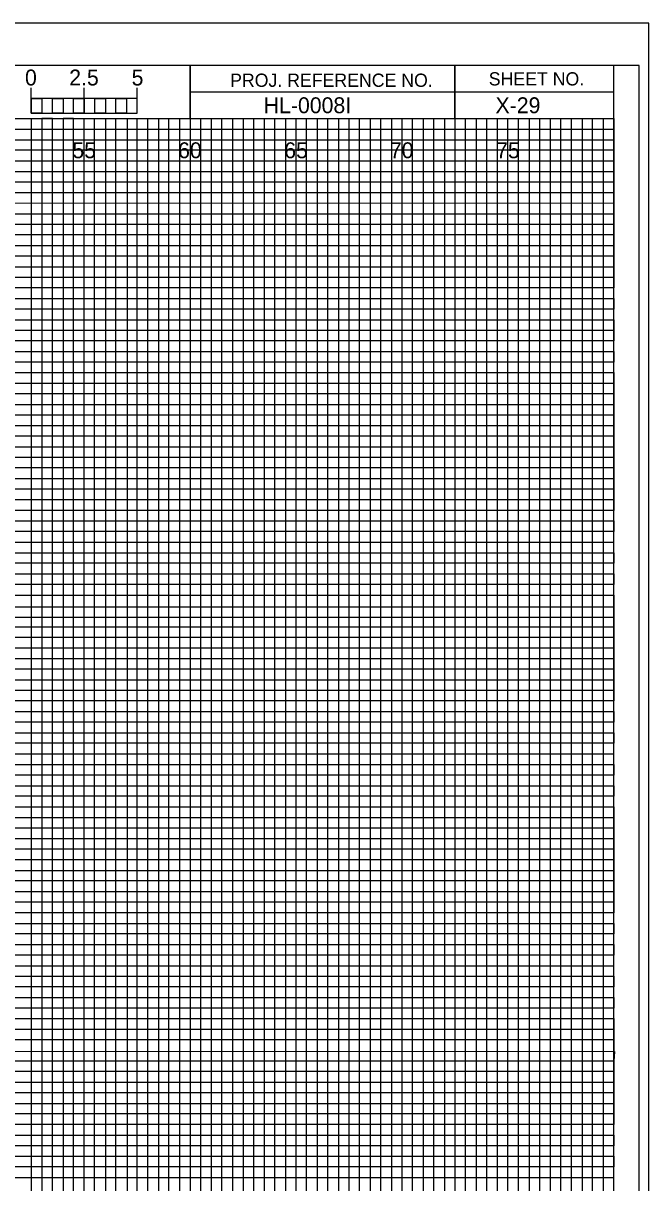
# Model space of a CAD drawing. Extents: x -7 to 162, y -2 to 217.
# Drawn here: x 132.1 to 161.7, y 162.2 to 217 of the extents above; entities that cross this region are included whole.
import ezdxf

# ---------------------------------------------------------------- set-up
doc = ezdxf.new("R2010")
doc.units = 0
for name, color, linetype in [('Exist Cross Section Cell', 7, 'Continuous'), ('Exist XS Center Line Elevation Label', 7, 'Continuous'), ('Exist XS Ground Line', 7, 'Continuous'), ('Prop CMT Pvmt Course 1 CG', 7, 'Continuous'), ('Prop CMT Pvmt Course 2', 7, 'Continuous'), ('Prop CMT Pvmt Course 3', 7, 'Continuous'), ('Prop CMT Shld Paved Course 1', 7, 'Continuous'), ('Prop CMT Shld Paved Course 2', 7, 'Continuous'), ('Prop CMT Shld Paved Course 3', 7, 'Continuous'), ('Prop CMT Slope Grass', 7, 'Continuous'), ('Prop CMT Subgrade Earthwork', 7, 'Continuous'), ('Scratch_Level_3', 7, 'Continuous')]:
    doc.layers.add(name, color=color, linetype=linetype)

msp = doc.modelspace()

# ---------------------------------------------------------------- linework, layer by layer
at = {"layer": 'Prop CMT Pvmt Course 2'}
msp.add_line((0, 212), (160, 212), dxfattribs=at)
for points in [[(0, 211.5), (135, 211.5), (160, 211.5)], [(160, 211), (0, 211)], [(0, 210.5), (160, 210.5)], [(160, 209.5), (0, 209.5)], [(0, 209), (160, 209)], [(160, 208.5), (0, 208.49)], [(0, 208), (160, 208)], [(160, 207), (0, 207)], [(0, 206.5), (160, 206.5), (160, 206), (0, 206)], [(0, 205.5), (160, 205.5), (160, 204.5), (0, 204.5)], [(0, 204), (160, 204), (160, 203.5), (0, 203.5)], [(0, 203), (160, 203), (160, 202), (0, 202)], [(0, 201.5), (160, 201.5), (160, 201), (0, 201)], [(0, 200.5), (160, 200.5), (160, 199.5), (0, 199.5)], [(0, 199), (160, 199), (160, 198.5), (0, 198.5)], [(0, 198), (160, 198), (160, 196.975), (160, 196.5), (160, 196), (0, 196)], [(0, 197), (160, 197), (160, 196.5), (0, 196.5)], [(0, 195.5), (160, 195.5), (160, 194.5), (0, 194.515)], [(0, 194.515), (160, 194.5), (160, 194), (0, 194)], [(0, 193.5), (160, 193.5), (160, 193), (0, 193)], [(0, 192), (160, 192), (160, 191.5), (0, 191.5)], [(0, 191), (160, 191), (160, 190.5), (0, 190.5)], [(-0.035, 189.445), (160, 189.445), (160, 188.94), (-0.035, 188.94)], [(0, 188.5), (160, 188.5), (160, 188), (0, 188)], [(0, 187), (160, 187), (160, 186.5), (0, 186.5)], [(0, 186), (160, 186), (160, 185.5), (0, 185.5)], [(0, 184.5), (160, 184.5), (160, 184), (0, 184)], [(0, 183.5), (160, 183.5), (160, 183), (0, 183)], [(0, 182), (160, 182), (160, 181.5), (0, 181.5)], [(0, 181), (160, 181), (160, 180.5), (0, 180.5)], [(0, 179.5), (160, 179.5), (159.995, 178.99), (0, 179)], [(0, 178.5), (160, 178.5), (160, 178), (0, 178)], [(0, 177), (160, 177), (160, 176.5), (0, 176.5)], [(0, 176), (160, 176), (160, 175.5), (0, 175.5)], [(0, 174.5), (160, 174.5), (160, 174), (0, 174)], [(0, 173.5), (160, 173.5), (160, 173), (0, 173)], [(0, 172), (160, 172), (160, 171.5), (0, 171.5)], [(0, 171), (160, 171), (160, 170.5), (0, 170.5)], [(0, 169.5), (160, 169.5), (160, 169), (0, 169)], [(0, 168.495), (160.035, 168.455), (160, 168), (0, 168)], [(0, 167), (160, 167), (160, 166.5), (0, 166.5)], [(0, 166), (160, 166), (160, 165.5), (0, 165.5)], [(0, 164.5), (160, 164.5), (160, 164), (0, 164)], [(0, 163.5), (160, 163.5), (160, 163), (0, 163)]]:
    msp.add_lwpolyline(points, dxfattribs=at)
at = {"layer": 'Prop CMT Pvmt Course 3'}
for p, q in [((135, 110), (135, 212.5)), ((140, 212.5), (140, 110)), ((145, 110), (145, 212.5)), ((150, 212.5), (150, 110)), ((155, 110), (155, 212.5))]:
    msp.add_line(p, q, dxfattribs=at)
for points in [[(160, 212.5), (160, 205), (0, 205)], [(0, 210), (160, 210)], [(0, 200), (160, 200), (160, 195), (0, 195)], [(0, 190), (160, 190), (160, 185), (0, 185)], [(0, 180), (160, 180), (160, 175), (0, 175)], [(0, 170), (160, 170), (160, 165), (0, 165)]]:
    msp.add_lwpolyline(points, dxfattribs=at)
at = {"layer": 'Prop CMT Shld Paved Course 1'}
msp.add_lwpolyline([(-6.7, 107.5), (161.65, 107.5), (161.65, 217), (-6.7, 217)], close=True, dxfattribs=at)
at = {"layer": 'Prop CMT Shld Paved Course 2'}
msp.add_lwpolyline([(-5.4, 109.5), (161.2, 109.5), (161.2, 215), (-5.4, 215)], close=True, dxfattribs=at)
at = {"layer": 'Prop CMT Shld Paved Course 3'}
for points in [[(127.5, 215), (129.965, 215), (130, 215), (130, 212.5), (132.495, 212.5), (132.495, 110), (137.5, 110), (137.5, 212.5), (140, 212.5)], [(0, 212.5), (137.5, 212.5)], [(0, 202.5), (160, 202.5), (160, 212.5)], [(142.5, 212.5), (142.5, 110), (147.5, 110), (147.5, 212.5)], [(152.5, 212.5), (152.5, 110), (157.5, 110), (157.5, 212.5)], [(160, 207.5), (0, 207.5)], [(0, 192.5), (160, 192.5), (160, 197.5), (0, 197.5)], [(0, 182.5), (160, 182.5), (160, 187.5), (0, 187.5)], [(0, 172.5), (160, 172.5), (160, 177.5), (0, 177.5)], [(0, 162.5), (160, 162.5), (160, 167.5), (0, 167.5)]]:
    msp.add_lwpolyline(points, dxfattribs=at)
at = {"layer": 'Prop CMT Slope Grass'}
for p, q in [((132.5, 212.745), (132.5, 213.95)), ((132.5, 213.45), (132.5, 213.95)), ((135, 212.745), (135, 213.95)), ((137.5, 212.745), (137.5, 213.95)), ((137.5, 213.45), (137.5, 213.95))]:
    msp.add_line(p, q, dxfattribs=at)
for points in [[(137.5, 213.45), (132.5, 213.45), (132.5, 212.745), (137.5, 212.745)], [(132.5, 213.45), (133, 213.45), (133, 212.745), (132.5, 212.745)], [(133.5, 213.45), (134, 213.45), (134, 212.745), (133.5, 212.745)], [(134.5, 213.45), (135, 213.45), (135, 212.745), (134.5, 212.745)], [(135.5, 213.45), (136, 213.45), (136, 212.745), (135.5, 212.745)], [(136.5, 213.45), (137, 213.45), (137, 212.745), (136.5, 212.745)]]:
    msp.add_lwpolyline(points, close=True, dxfattribs=at)
at = {"layer": 'Prop CMT Subgrade Earthwork'}
for p, q in [((133.5, 212.5), (133.005, 212.5)), ((133.005, 212.5), (133.005, 110)), ((133.5, 110), (133.5, 212.5)), ((134.5, 212.5), (134, 212.5)), ((134, 212.5), (134, 110)), ((134.5, 110), (134.5, 212.5))]:
    msp.add_line(p, q, dxfattribs=at)
for points in [[(135, 110), (135.49, 110), (135.49, 212.5), (136, 212.5), (136, 110)], [(136, 110), (136.5, 110), (136.5, 212.5), (137.025, 212.5), (137.025, 110)], [(137.5, 110), (138, 110), (138, 212.5), (138.5, 212.5), (138.5, 110)], [(138.5, 110), (139, 110), (139, 212.5), (139.5, 212.5), (139.5, 110)], [(140, 110), (140.5, 110), (140.5, 212.5)], [(141, 212.5), (141, 110)], [(141, 110), (141.5, 110), (141.5, 212.5)], [(142, 212.5), (142, 110)], [(142.5, 110), (143, 110), (143, 212.5)], [(143.5, 212.5), (143.5, 110)], [(143.5, 110), (144, 110), (144, 212.5)], [(144.5, 212.5), (144.5, 110)], [(145, 110), (145.5, 110), (145.5, 212.5)], [(146, 212.5), (146, 110)], [(146, 110), (146.5, 110), (146.5, 212.5)], [(147, 212.5), (147, 110)], [(147.5, 110), (148, 110), (148, 212.5)], [(148.5, 212.5), (148.5, 110)], [(148.5, 110), (149, 110), (149, 212.5)], [(149.5, 212.5), (149.5, 110)], [(150, 110), (150.5, 110), (150.5, 212.5)], [(151, 212.5), (151, 110)], [(151, 110), (151.5, 110), (151.5, 212.5)], [(152, 212.5), (152, 110)], [(152.5, 110), (153, 110), (153, 212.5)], [(153.5, 212.5), (153.5, 110)], [(153.5, 110), (154, 110), (154, 212.5)], [(154.5, 212.5), (154.5, 110)], [(155, 110), (155.5, 110), (155.5, 212.5)], [(156, 212.5), (156, 110)], [(156, 110), (156.5, 110), (156.5, 212.5)], [(157, 212.5), (157, 110)], [(157.5, 110), (158, 110), (158, 212.5)], [(158.5, 212.5), (158.5, 110)], [(158.5, 110), (159, 110), (159, 212.5)], [(159.5, 212.5), (159.5, 110)]]:
    msp.add_lwpolyline(points, dxfattribs=at)
at = {"layer": 'Scratch_Level_3'}
for p, q in [((152.5, 215), (152.5, 212.5)), ((152.5, 212.5), (152.5, 215)), ((140, 213.75), (140, 212.5)), ((160, 213.745), (140, 213.745)), ((140, 212.5), (160, 212.5))]:
    msp.add_line(p, q, dxfattribs=at)
for points in [[(160, 215), (0, 215), (0, 110), (160, 110)], [(140, 215), (130, 215), (130, 212.5), (140, 212.5)], [(160, 215), (140, 215), (140, 212.5), (160, 212.5)]]:
    msp.add_lwpolyline(points, close=True, dxfattribs=at)

# ---------------------------------------------------------------- texts
at = {"layer": 'Exist Cross Section Cell'}
for s, p in [('55', (134.441, 210.625)), ('60', (139.429, 210.625)), ('65', (144.441, 210.625)), ('70', (149.429, 210.625)), ('75', (154.441, 210.625))]:
    msp.add_text(s, height=0.75, dxfattribs=at).set_placement(p)
at = {"layer": 'Exist XS Center Line Elevation Label'}
msp.add_text('HL-0008I', height=0.75, dxfattribs=at).set_placement((143.474, 212.75))
at = {"layer": 'Exist XS Ground Line'}
msp.add_text('X-29', height=0.75, dxfattribs=at).set_placement((154.415, 212.75))
at = {"layer": 'Prop CMT Pvmt Course 1 CG'}
for s, p in [('2.5', (134.292, 214.06)), ('5', (137.237, 214.06))]:
    msp.add_text(s, height=0.75, dxfattribs=at).set_placement(p)
at = {"layer": 'Prop CMT Slope Grass'}
msp.add_text('0', height=0.75, rotation=360, dxfattribs=at).set_placement((132.205, 214.06))
at = {"layer": 'Scratch_Level_3'}
for s, height, p in [('PROJ. REFERENCE NO.', 0.62499, (141.885, 213.995)), ('SHEET NO.', 0.625, (154.095, 214.06))]:
    msp.add_text(s, height=height, rotation=360, dxfattribs=at).set_placement(p)

doc.saveas('drawing.dxf')
